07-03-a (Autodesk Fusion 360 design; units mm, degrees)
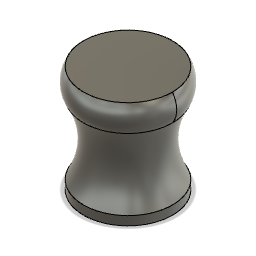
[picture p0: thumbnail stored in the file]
sketch "スケッチ1" plane through (0, 0, 0) normal (0, 1, 0) x axis (1, 0, 0)
  circle C1 centre (0, 0) radius 25
  point P1 (0, 0)
  point P2 (0, 0)
  coincident P1 P2
  dimension "d1" diameter C1 = 50
extrude "押し出し" new body sketch "スケッチ1" along normal blind 5
work_plane "作業平面1" AlongDistance 20
sketch "スケッチ2" plane through (0, 25, 0) normal (0, 1, 0) x axis (1, 0, 0)
  circle C1 centre (0, 0) radius 20
  point P1 (0, 0)
  point P2 (0, 0)
  coincident P1 P2
  dimension "d5" diameter C1 = 40
work_plane "作業平面2" AlongDistance 20
sketch "スケッチ3" plane through (0, 45, 0) normal (0, 1, 0) x axis (1, 0, 0)
  circle C1 centre (0, 0) radius 25
loft "ロフト1" sketch "スケッチ2" + "スケッチ3"
work_plane "作業平面3" AlongDistance 15
sketch "スケッチ4" plane through (0, 60, 0) normal (0, 1, 0) x axis (1, 0, 0)
  circle C1 centre (0, 0) radius 25
sketch "スケッチ5" plane through (0, 0, 0) normal (0, 0, 1) x axis (1, 0, 0)
  line L1 (-25, 60) -> (25, 60)
  line L2 (25, 45) -> (-25, 45)
  arc A1 centre (-14.3816, 52.5) radius 13 clockwise from (-25, 45) to (-25, 60)
  arc A2 centre (14.3816, 52.5) radius 13 clockwise from (25, 60) to (25, 45)
  point P2 (-25, 60)
  point P9 (-25, 60)
  point P3 (-25, 45)
  point P10 (-25, 45)
  point P5 (25, 60)
  point P8 (25, 60)
  point P6 (25, 45)
  point P11 (25, 45)
  coincident P2 P9
  coincident P3 P10
  coincident P5 P8
  coincident P6 P11
  equal A1 A2
  dimension "d8" radius A1 = 13
sketch "スケッチ6" plane through (0, 0, 0) normal (1, 0, 0) x axis (0, 0, -1)
  line L1 (-25, 60) -> (25, 60)
  line L2 (25, 45) -> (-25, 45)
  arc A1 centre (-14.3816, 52.5) radius 13 clockwise from (-25, 45) to (-25, 60)
  arc A2 centre (14.3816, 52.5) radius 13 clockwise from (25, 60) to (25, 45)
  point P2 (-25, 60)
  point P9 (-25, 60)
  point P3 (-25, 45)
  point P10 (-25, 45)
  point P6 (25, 45)
  point P11 (25, 45)
  point P5 (25, 60)
  point P8 (25, 60)
  coincident P2 P9
  coincident P3 P10
  coincident P6 P11
  coincident P5 P8
  equal A1 A2
  dimension "d9" radius A1 = 13
loft "ロフト2" sketch "スケッチ4"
